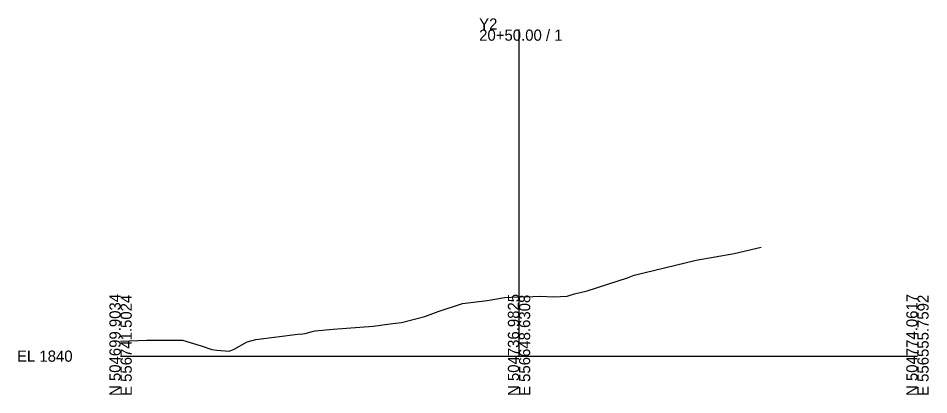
# Model space of a CAD drawing. Extents: x -26 to 203, y -10 to 3574.
# Drawn here: x -25.7 to 202.8, y 490.3 to 584.8 of the extents above; entities that cross this region are included whole.
import ezdxf

# ---------------------------------------------------------------- set-up
doc = ezdxf.new("R2010")
doc.units = 0
doc.layers.add('Exist Cross Section Cell', color=7, linetype='Continuous')
doc.layers.add('Exist XS Ground Line', color=7, linetype='Continuous')

msp = doc.modelspace()

# ---------------------------------------------------------------- linework, layer by layer
at = {"layer": 'Exist Cross Section Cell'}
for p, q in [((100, 500), (100, 581.93)), ((0, 500), (100, 500)), ((100, 500), (200, 500))]:
    msp.add_line(p, q, dxfattribs=at)
at = {"layer": 'Exist XS Ground Line'}
for p, q in [((144.45, 524.1), (154.02, 525.72)), ((154.02, 525.72), (160.8, 527.31)), ((128.89, 520.29), (144.45, 524.1)), ((117.06, 516.4), (127.24, 519.65)), ((127.24, 519.65), (128.89, 520.29)), ((91.99, 513.99), (96.36, 514.75)), ((96.36, 514.75), (99.64, 514.86)), ((99.64, 514.86), (100, 514.87)), ((100, 514.87), (103.5, 514.97)), ((103.5, 514.97), (105.3, 515.08)), ((105.3, 515.08), (108.7, 514.86)), ((108.7, 514.86), (112.1, 515.05)), ((112.1, 515.05), (112.56, 515.23)), ((112.56, 515.23), (113.96, 515.61)), ((113.96, 515.61), (117.06, 516.4)), ((79.74, 511.16), (85.83, 513.23)), ((85.83, 513.23), (91.99, 513.99)), ((70.49, 508.46), (76.32, 509.94)), ((76.32, 509.94), (79.74, 511.16)), ((53.36, 506.76), (63.39, 507.56)), ((63.39, 507.56), (67.68, 508.1)), ((67.68, 508.1), (70.49, 508.46)), ((33.98, 504.16), (44.52, 505.51)), ((44.52, 505.51), (45.78, 505.57)), ((45.78, 505.57), (46.31, 505.64)), ((46.31, 505.64), (48.4, 506.25)), ((48.4, 506.25), (48.85, 506.34)), ((48.85, 506.34), (53.36, 506.76)), ((0, 503.74), (6.48, 504.02)), ((6.48, 504.02), (15.5, 504.04)), ((15.5, 504.04), (20.24, 502.6)), ((28.53, 501.73), (31.76, 503.56)), ((31.76, 503.56), (33.98, 504.16)), ((20.24, 502.6), (22.92, 501.63)), ((22.92, 501.63), (24.18, 501.46)), ((24.18, 501.46), (27.26, 501.27)), ((27.26, 501.27), (28.53, 501.73))]:
    msp.add_line(p, q, dxfattribs=at)

# ---------------------------------------------------------------- texts
at = {"layer": 'Exist Cross Section Cell'}
for s, p in [('Y2', (90, 581.93)), ('20+50.00 / 1', (90, 579.13)), ('EL 1840', (-26, 498.6))]:
    msp.add_text(s, height=2.8, dxfattribs=at).set_placement(p)
for s, p in [('N 504699.9034', (0, 490)), ('E 556741.5024', (2.8, 490)), ('N 504736.9825', (100, 490)), ('E 556648.6308', (102.8, 490)), ('N 504774.0617', (200, 490)), ('E 556555.7592', (202.8, 490))]:
    msp.add_text(s, height=2.8, rotation=90, dxfattribs=at).set_placement(p)

doc.saveas('drawing.dxf')
